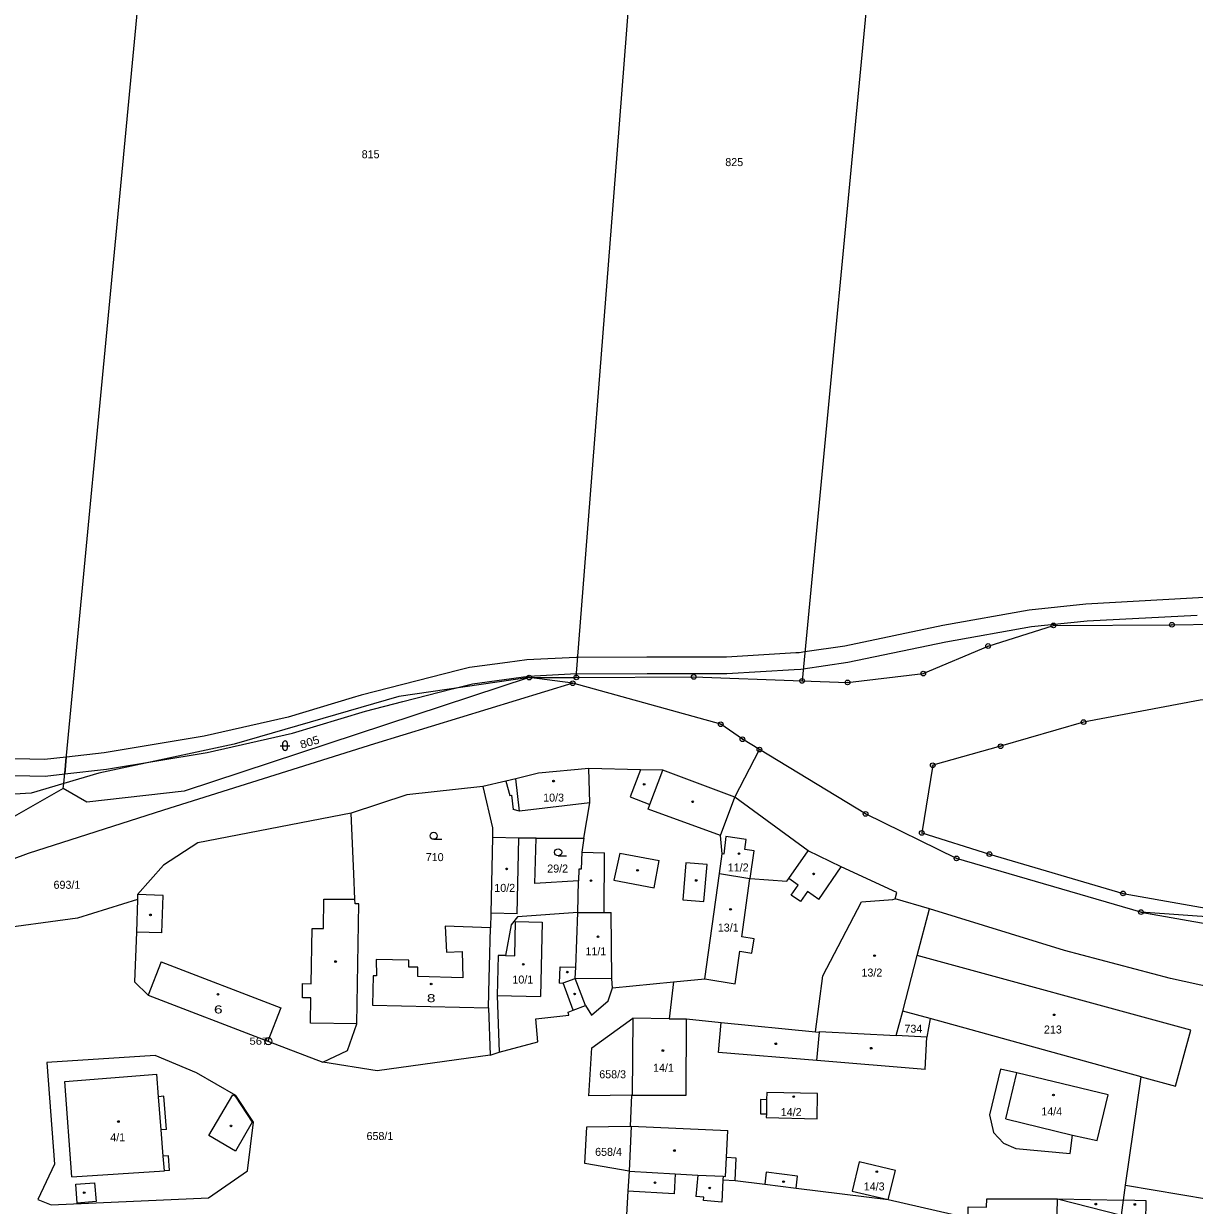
# Model space of a CAD drawing. Extents: x -758887 to -754328, y -1031688 to -1029144.
# Drawn here: x -756406 to -756157.4, y -1030298.3 to -1030047.3 of the extents above; entities that cross this region are included whole.
import ezdxf
from ezdxf.enums import TextEntityAlignment as Align

# ---------------------------------------------------------------- set-up
doc = ezdxf.new("R2010")
doc.units = 0
doc.header["$LTSCALE"] = 0.68
for name, color, linetype, lineweight in [('1', 7, 'Continuous', 25), ('13', 7, 'Continuous', 13), ('3', 7, 'Continuous', 25), ('4', 7, 'Continuous', 13), ('5', 7, 'Continuous', 25), ('8', 7, 'Continuous', 25)]:
    doc.layers.add(name, color=color, linetype=linetype, lineweight=lineweight)
doc.layers.add('2', color=7, linetype='Continuous')

msp = doc.modelspace()

# ---------------------------------------------------------------- linework, layer by layer
at = {"layer": '1'}
for p, q in [((-756298.64, -1030186.19), (-756288.65, -1030186.16)), ((-756289.4, -1030187.39), (-756298.64, -1030186.19)), ((-756254.97, -1030211.62), (-756249.73, -1030201.5)), ((-756397.61, -1030209.77), (-756397.5, -1030208.7)), ((-756308.5, -1030209.34), (-756324.6, -1030211.13)), ((-756324.6, -1030211.13), (-756336.44, -1030214.98)), ((-756239.39, -1030223), (-756254.97, -1030211.62)), ((-756297.13, -1030220.29), (-756287, -1030220.3)), ((-756288.32, -1030236.1), (-756288.15, -1030229.38)), ((-756381.8, -1030232.31), (-756381.84, -1030233.37)), ((-756115.36, -1030239.81), (-756168.69, -1030236.01)), ((-756306.88, -1030239.35), (-756316.51, -1030239.02)), ((-756237.83, -1030261.47), (-756236.27, -1030249.59)), ((-756268, -1030250.87), (-756268.93, -1030258.67)), ((-756307.27, -1030256.38), (-756306.89, -1030266.4)), ((-756220.67, -1030262.26), (-756219.3, -1030257.06)), ((-756213.48, -1030258.66), (-756219.3, -1030257.06)), ((-756268.93, -1030258.67), (-756276.6, -1030258.56)), ((-756342.5, -1030267.88), (-756337.26, -1030265.43)), ((-756306.89, -1030266.4), (-756304.98, -1030265.8)), ((-756276.93, -1030274.93), (-756285.96, -1030275.08)), ((-756186.43, -1030296.97), (-756172.41, -1030297.26)), ((-756186.43, -1030296.97), (-756172.86, -1030300.43)), ((-756172.86, -1030300.43), (-756172.41, -1030297.26))]:
    msp.add_line(p, q, dxfattribs=at)
for points in [[(-756397.5, -1030208.7), (-756385.26, -1030080.23), (-756373.02, -1029951.75)], [(-756288.65, -1030186.16), (-756279.98, -1030074.99), (-756271.3, -1029963.81)], [(-756219.98, -1029969.89), (-756230.34, -1030078.39), (-756240.69, -1030186.89)], [(-755912.98, -1030131.91), (-755941.48, -1030149.18), (-755969.92, -1030165.14), (-755979.24, -1030168.83), (-756000.09, -1030175.58), (-756023.31, -1030180.26), (-756045.55, -1030182.98), (-756110.5, -1030186.46), (-756122.46, -1030187.46), (-756156.09, -1030190.98), (-756180.89, -1030195.65), (-756198.51, -1030200.79), (-756212.93, -1030204.83), (-756215.25, -1030219.21), (-756200.88, -1030223.69), (-756172.51, -1030232.07), (-756144.45, -1030237.03), (-756115.36, -1030239.81)], [(-756397.5, -1030208.7), (-756404.43, -1030210.74), (-756423.36, -1030211.9), (-756445.13, -1030205.02), (-756460.1, -1030199.16), (-756472.56, -1030191.89), (-756481.5, -1030181.55), (-756483.07, -1030159.02)], [(-756397.61, -1030209.77), (-756413.06, -1030218.58), (-756424.18, -1030217.91), (-756448.29, -1030208.09), (-756458.95, -1030202.48), (-756478.73, -1030190.1), (-756487.17, -1030180.84), (-756487.51, -1030172.18)], [(-756240.69, -1030186.89), (-756231.02, -1030187.24), (-756214.93, -1030185.36), (-756201.16, -1030179.49), (-756187.28, -1030175.13), (-756162.13, -1030174.98), (-756134.72, -1030174.56), (-756116.1, -1030171.61), (-756107.99, -1030171.7), (-756103.62, -1030173.4), (-756090.76, -1030175.31), (-756046.25, -1030174.07)], [(-756289.4, -1030187.39), (-756331.47, -1030200.27), (-756376.31, -1030214.36), (-756405.07, -1030223.59), (-756412.88, -1030226.49), (-756423.07, -1030227.94), (-756433.13, -1030224.17), (-756441.53, -1030224.23)], [(-756298.64, -1030186.19), (-756371.89, -1030210.3), (-756392.61, -1030212.65), (-756397.61, -1030209.77)], [(-756298.64, -1030186.19), (-756326.33, -1030190.22), (-756361.32, -1030200.34), (-756390.05, -1030206.51), (-756397.5, -1030208.7)], [(-756249.73, -1030201.5), (-756253.34, -1030199.31), (-756257.96, -1030196.12), (-756289.4, -1030187.39)], [(-756288.65, -1030186.16), (-756263.67, -1030186.07), (-756240.69, -1030186.89)], [(-756168.69, -1030236.01), (-756207.87, -1030224.63), (-756227.19, -1030215.16), (-756249.73, -1030201.5)], [(-756285.94, -1030205.54), (-756296.67, -1030206.53), (-756301.49, -1030207.68), (-756303.63, -1030208.19), (-756308.5, -1030209.34)], [(-756287, -1030220.3), (-756285.78, -1030212.8), (-756285.94, -1030205.54)], [(-756254.97, -1030211.62), (-756270.23, -1030205.88), (-756275.01, -1030205.78), (-756285.94, -1030205.54)], [(-756308.5, -1030209.34), (-756306.42, -1030218.15), (-756306.43, -1030220.16)], [(-756258.25, -1030227.8), (-756257.66, -1030223.64), (-756258.03, -1030219.77), (-756254.97, -1030211.62)], [(-756336.44, -1030214.98), (-756369.05, -1030221.33), (-756376.28, -1030226.02), (-756381.8, -1030232.31)], [(-756337.26, -1030265.43), (-756335.21, -1030259.75), (-756334.8, -1030234.3), (-756335.6, -1030234.29), (-756335.64, -1030233.31), (-756335.87, -1030227.92), (-756336.44, -1030214.98)], [(-756306.43, -1030220.16), (-756306.8, -1030236.25), (-756306.88, -1030239.35)], [(-756297.13, -1030220.29), (-756300.83, -1030220.29), (-756306.43, -1030220.16)], [(-756288.15, -1030229.38), (-756297.43, -1030229.96), (-756297.13, -1030220.29)], [(-756287, -1030220.3), (-756287.49, -1030223.3), (-756287.58, -1030226.9), (-756288.08, -1030226.88), (-756288.15, -1030229.38)], [(-756258.25, -1030227.8), (-756251.77, -1030228.9), (-756251.68, -1030228.91), (-756243.9, -1030229.43), (-756243.5, -1030228.86), (-756239.39, -1030223)], [(-756220.87, -1030233.23), (-756220.54, -1030231.86), (-756232.36, -1030226.44), (-756239.39, -1030223)], [(-756268, -1030250.87), (-756261.35, -1030250.22), (-756258.25, -1030227.8)], [(-756381.84, -1030233.37), (-756394.55, -1030237.3), (-756413.41, -1030239.85)], [(-756381.84, -1030233.37), (-756382.07, -1030240.27), (-756382.44, -1030250.86)], [(-756236.27, -1030249.59), (-756228.08, -1030233.83), (-756221.43, -1030233.35), (-756220.87, -1030233.23)], [(-756219.3, -1030257.06), (-756216.2, -1030245.25), (-756213.6, -1030235.35), (-756220.87, -1030233.23)], [(-756108.96, -1030258.41), (-756110.66, -1030258.34), (-756131.11, -1030256.31), (-756143.73, -1030254.26), (-756162.39, -1030250.16), (-756184.91, -1030244.16), (-756213.6, -1030235.35)], [(-756288.32, -1030236.1), (-756301.15, -1030237.06), (-756302.45, -1030238.75), (-756303.7, -1030245.28), (-756305.25, -1030245.24), (-756305.45, -1030253.74), (-756304.98, -1030265.8)], [(-756286.68, -1030255.9), (-756288.84, -1030250.1), (-756288.75, -1030247.74), (-756288.32, -1030236.1)], [(-756168.69, -1030236.01), (-756107.58, -1030246.78), (-756057.43, -1030250.7), (-755984.58, -1030253.93), (-755948, -1030254.04), (-755899.3, -1030254.19), (-755881.67, -1030257.6), (-755833.91, -1030271.8), (-755782.97, -1030285.7), (-755758.24, -1030294.36)], [(-756316.51, -1030239.02), (-756316.2, -1030244.55), (-756312.9, -1030244.36)], [(-756307.27, -1030256.38), (-756307.13, -1030250.08), (-756307.07, -1030247.55), (-756306.88, -1030239.35)], [(-756312.9, -1030244.36), (-756312.7, -1030249.96), (-756322.31, -1030249.74), (-756322.28, -1030247.74)], [(-756168.68, -1030270.99), (-756161.37, -1030273), (-756158.12, -1030261.08), (-756216.2, -1030245.25)], [(-756331.11, -1030246.12), (-756331.05, -1030249.55), (-756331.81, -1030249.53), (-756331.95, -1030255.83), (-756307.27, -1030256.38)], [(-756322.28, -1030247.74), (-756324.2, -1030247.69), (-756324.17, -1030246.23), (-756331.11, -1030246.12)], [(-756382.44, -1030250.86), (-756379.54, -1030253.67), (-756354.12, -1030263.47), (-756342.5, -1030267.88)], [(-756286.68, -1030255.9), (-756285.43, -1030257.95), (-756281.89, -1030254.87), (-756280.94, -1030252.14), (-756268, -1030250.87)], [(-756304.98, -1030265.8), (-756296.79, -1030263.57), (-756297.23, -1030258.67), (-756290.19, -1030257.94), (-756290.36, -1030257.26), (-756289.27, -1030256.86), (-756286.68, -1030255.9)], [(-756285.96, -1030275.08), (-756285.33, -1030264.89), (-756276.6, -1030258.56)], [(-756276.6, -1030258.56), (-756276.73, -1030274.93), (-756276.93, -1030274.93), (-756277.16, -1030281.48)], [(-756268.93, -1030258.67), (-756265.21, -1030258.72), (-756257.88, -1030259.46), (-756237.83, -1030261.47)], [(-756213.48, -1030258.66), (-756214.17, -1030262.6), (-756220.67, -1030262.26)], [(-756172.41, -1030297.26), (-756171.95, -1030294.02), (-756168.68, -1030270.99), (-756213.48, -1030258.66)], [(-756171.95, -1030294.02), (-756136.72, -1030299.99), (-756110.94, -1030301.63), (-756111.35, -1030284.16), (-756108.96, -1030258.41)], [(-756237.83, -1030261.47), (-756237, -1030261.54), (-756236.99, -1030261.41), (-756220.67, -1030262.26)], [(-756306.89, -1030266.4), (-756330.93, -1030269.74), (-756342.5, -1030267.88)], [(-756277.43, -1030291.05), (-756286.84, -1030289.47), (-756286.36, -1030281.68), (-756277.16, -1030281.48)], [(-756277.16, -1030281.48), (-756276.96, -1030281.48), (-756277.43, -1030291.05)], [(-756220.86, -1030290.89), (-756228.52, -1030289.05), (-756230.01, -1030295.28)], [(-756277.43, -1030291.05), (-756277.68, -1030295.34), (-756278.04, -1030301.63)], [(-756277.43, -1030291.05), (-756267.6, -1030291.62), (-756262.8, -1030291.89), (-756257.46, -1030292.14), (-756257.5, -1030292.9), (-756254.89, -1030293.02), (-756248.59, -1030293.81), (-756241.94, -1030294.65), (-756222.37, -1030297.12), (-756205.42, -1030300.96), (-756205.39, -1030298.66), (-756201.49, -1030298.72), (-756201.46, -1030296.97), (-756186.43, -1030296.97)], [(-756230.01, -1030295.28), (-756222.37, -1030297.12), (-756220.86, -1030290.89)], [(-756187.15, -1030337.79), (-756187.28, -1030336.24), (-756187.11, -1030328.19), (-756186.43, -1030296.97)], [(-756167.68, -1030301.76), (-756167.6, -1030297.36), (-756172.41, -1030297.26)]]:
    msp.add_lwpolyline(points, dxfattribs=at)
for points in [[(-756402.99, -1030297.09), (-756400.2, -1030298.24), (-756366.72, -1030296.7), (-756358.44, -1030291.01), (-756357.22, -1030280.65), (-756360.95, -1030274.96), (-756369.31, -1030270.17), (-756378.05, -1030266.48), (-756401.1, -1030267.97), (-756399.46, -1030289.6)], [(-756178.02, -1030284.55), (-756175.64, -1030274.87), (-756195.04, -1030270.2), (-756198.52, -1030269.37), (-756200.84, -1030279.1), (-756199.99, -1030282.84), (-756197.89, -1030285.09), (-756195.27, -1030286.27), (-756183.75, -1030287.3), (-756183.22, -1030283.41)], [(-756249.53, -1030278.85), (-756248.26, -1030278.87), (-756248.27, -1030279.68), (-756237.45, -1030279.95), (-756237.4, -1030274.6), (-756248.19, -1030274.38), (-756248.21, -1030275.89), (-756249.48, -1030275.87)]]:
    msp.add_lwpolyline(points, close=True, dxfattribs=at)
at = {"layer": '13'}
for points in [[(-756147.68, -1030168.74), (-756180.38, -1030170.62), (-756192.44, -1030171.88), (-756210.77, -1030175.15), (-756231.6, -1030179.5), (-756240.1, -1030180.75), (-756241.27, -1030180.92), (-756241.99, -1030180.96), (-756256.74, -1030181.84), (-756273.62, -1030181.83), (-756288.3, -1030181.92), (-756288.32, -1030181.92), (-756288.63, -1030181.92), (-756299.13, -1030182.44), (-756303.23, -1030182.98), (-756311.34, -1030184.06), (-756313.61, -1030184.64), (-756334.36, -1030189.96), (-756336.21, -1030190.52), (-756349.81, -1030194.63), (-756367.68, -1030198.65), (-756388.89, -1030202.17), (-756396.91, -1030203.09), (-756396.97, -1030203.1), (-756397.3, -1030206.65), (-756397.28, -1030206.65), (-756388.41, -1030205.63), (-756377.73, -1030203.86), (-756367, -1030202.09), (-756348.91, -1030198.01), (-756333.42, -1030193.34), (-756325.5, -1030191.31), (-756315.01, -1030188.61), (-756314.65, -1030188.52), (-756310.68, -1030187.5), (-756298.81, -1030185.92), (-756288.59, -1030185.36), (-756288.53, -1030185.42), (-756273.6, -1030185.33), (-756256.64, -1030185.34), (-756242.36, -1030184.49), (-756240.91, -1030184.4), (-756240.45, -1030184.33), (-756230.98, -1030182.94), (-756210.11, -1030178.59), (-756191.96, -1030175.34), (-756180.1, -1030174.12), (-756156.78, -1030172.92)], [(-756411.37, -1030206.9), (-756401.43, -1030207.12), (-756397.3, -1030206.65), (-756396.97, -1030203.1), (-756401.59, -1030203.62), (-756411.03, -1030203.4)]]:
    msp.add_lwpolyline(points, dxfattribs=at)
at = {"layer": '3'}
for p, q in [((-756351.001, -1030200.171), (-756351.001, -1030201.172)), ((-756349.999, -1030201.172), (-756349.999, -1030200.171)), ((-756351.501, -1030200.671), (-756349.499, -1030200.671)), ((-756318.923, -1030220.56), (-756317.173, -1030220.56)), ((-756292.483, -1030224.07), (-756290.733, -1030224.07))]:
    msp.add_line(p, q, dxfattribs=at)
for centre in [(-756318.9229, -1030219.8098), (-756292.4829, -1030223.3198)]:
    msp.add_circle(centre, 0.75, dxfattribs=at)
for centre, start, end in [((-756350.5, -1030200.1709), 0, 180), ((-756350.5, -1030201.1709), 180, 359.98789)]:
    msp.add_arc(centre, 0.5, start, end, dxfattribs=at)
at = {"layer": '4'}
for p, q in [((-756300.68, -1030214.55), (-756301.49, -1030207.68)), ((-756275.01, -1030205.78), (-756277.19, -1030211.54)), ((-756272.98, -1030213.13), (-756270.23, -1030205.88)), ((-756303.63, -1030208.19), (-756302.74, -1030211.22)), ((-756302.74, -1030211.22), (-756302.39, -1030211.18)), ((-756302.39, -1030211.18), (-756302.02, -1030214.26)), ((-756285.78, -1030212.8), (-756300.68, -1030214.55)), ((-756277.19, -1030211.54), (-756272.98, -1030213.13)), ((-756300.68, -1030214.55), (-756302.02, -1030214.26)), ((-756273.37, -1030214.16), (-756272.98, -1030213.13)), ((-756258.03, -1030219.77), (-756273.37, -1030214.16)), ((-756301.2, -1030236.38), (-756300.83, -1030220.29)), ((-756287.49, -1030223.3), (-756282.67, -1030223.42)), ((-756282.7, -1030236.11), (-756282.67, -1030223.42)), ((-756279.39, -1030223.47), (-756271.02, -1030225.06)), ((-756257.32, -1030223.69), (-756257.66, -1030223.64)), ((-756265.36, -1030225.55), (-756266.03, -1030233.4)), ((-756260.85, -1030225.93), (-756265.36, -1030225.55)), ((-756261.52, -1030233.78), (-756260.85, -1030225.93)), ((-756237.13, -1030233.33), (-756232.36, -1030226.44)), ((-756253.46, -1030241.29), (-756251.77, -1030228.9)), ((-756241.49, -1030230.27), (-756243.5, -1030228.86)), ((-756242.99, -1030232.4), (-756241.49, -1030230.27)), ((-756376.4, -1030232.5), (-756381.8, -1030232.31)), ((-756376.68, -1030240.45), (-756376.4, -1030232.5)), ((-756241.02, -1030233.77), (-756242.99, -1030232.4)), ((-756342.29, -1030239.49), (-756342.23, -1030233.26)), ((-756342.23, -1030233.26), (-756335.64, -1030233.31)), ((-756266.03, -1030233.4), (-756261.52, -1030233.78)), ((-756301.2, -1030236.38), (-756306.8, -1030236.25)), ((-756281.1, -1030250.22), (-756281.2, -1030236.1)), ((-756376.68, -1030240.45), (-756382.07, -1030240.27)), ((-756301.54, -1030238.02), (-756295.89, -1030238.15)), ((-756295.89, -1030238.15), (-756296.25, -1030253.95)), ((-756376.81, -1030246.58), (-756379.54, -1030253.67)), ((-756376.81, -1030246.58), (-756351.39, -1030256.38)), ((-756292.18, -1030251.12), (-756292.06, -1030247.62)), ((-756292.06, -1030247.62), (-756288.75, -1030247.74)), ((-756291.43, -1030251.06), (-756288.84, -1030250.1)), ((-756281.1, -1030250.22), (-756288.84, -1030250.1)), ((-756280.94, -1030252.14), (-756281.1, -1030250.22)), ((-756261.35, -1030250.22), (-756254.92, -1030251.24)), ((-756292.18, -1030251.12), (-756291.43, -1030251.06)), ((-756289.27, -1030256.86), (-756291.43, -1030251.06)), ((-756305.45, -1030253.74), (-756296.25, -1030253.95)), ((-756351.39, -1030256.38), (-756354.12, -1030263.47)), ((-756265.28, -1030274.95), (-756265.21, -1030258.72)), ((-756258.41, -1030265.82), (-756257.88, -1030259.46)), ((-756237.53, -1030267.57), (-756237, -1030261.54)), ((-756214.53, -1030269.49), (-756214.17, -1030262.6)), ((-756237.53, -1030267.57), (-756258.41, -1030265.82)), ((-756214.53, -1030269.49), (-756237.53, -1030267.57)), ((-756397.28, -1030272.01), (-756377.71, -1030270.49)), ((-756377.34, -1030275.24), (-756377.71, -1030270.49)), ((-756197.39, -1030279.92), (-756195.04, -1030270.2)), ((-756395.76, -1030292.28), (-756397.28, -1030272.01)), ((-756376.25, -1030275.15), (-756377.34, -1030275.24)), ((-756376.8, -1030282.3), (-756377.34, -1030275.24)), ((-756375.7, -1030282.21), (-756376.25, -1030275.15)), ((-756276.73, -1030274.93), (-756265.28, -1030274.95)), ((-756248.21, -1030275.89), (-756248.26, -1030278.87)), ((-756197.39, -1030279.92), (-756183.22, -1030283.41)), ((-756375.7, -1030282.21), (-756376.8, -1030282.3)), ((-756376.36, -1030287.9), (-756376.8, -1030282.3)), ((-756276.96, -1030281.48), (-756256.45, -1030282.44)), ((-756375.27, -1030287.82), (-756376.36, -1030287.9)), ((-756376.12, -1030290.99), (-756376.36, -1030287.9)), ((-756375.03, -1030290.91), (-756375.27, -1030287.82)), ((-756256.91, -1030292.17), (-756256.72, -1030288.18)), ((-756254.89, -1030293.02), (-756254.67, -1030288.28)), ((-756395.76, -1030292.28), (-756376.12, -1030290.99)), ((-756375.03, -1030290.91), (-756376.12, -1030290.99)), ((-756262.8, -1030291.89), (-756263.23, -1030296.43)), ((-756257.5, -1030292.9), (-756257.72, -1030297.65)), ((-756257.46, -1030292.14), (-756256.91, -1030292.17)), ((-756248.27, -1030291.28), (-756248.59, -1030293.81)), ((-756241.62, -1030292.12), (-756248.27, -1030291.28)), ((-756241.94, -1030294.65), (-756241.62, -1030292.12)), ((-756261.54, -1030296.59), (-756263.23, -1030296.43)), ((-756261.6, -1030297.29), (-756261.54, -1030296.59)), ((-756257.72, -1030297.65), (-756261.6, -1030297.29))]:
    msp.add_line(p, q, dxfattribs=at)
for points in [[(-756251.68, -1030228.91), (-756250.82, -1030223), (-756252.85, -1030222.73), (-756252.53, -1030220.62), (-756256.84, -1030219.93), (-756257.32, -1030223.69)], [(-756279.39, -1030223.47), (-756280.65, -1030229.23), (-756272.12, -1030230.84), (-756271.02, -1030225.06)], [(-756237.13, -1030233.33), (-756239.53, -1030231.64), (-756241.02, -1030233.77)], [(-756288.32, -1030236.1), (-756282.7, -1030236.11), (-756281.2, -1030236.1)], [(-756346.79, -1030251.2), (-756344.95, -1030251.23), (-756344.74, -1030239.48), (-756342.29, -1030239.49)], [(-756303.7, -1030245.28), (-756301.7, -1030245.32), (-756301.54, -1030238.02)], [(-756254.92, -1030251.24), (-756253.91, -1030244.35), (-756251.34, -1030244.78), (-756250.85, -1030241.71), (-756253.46, -1030241.29)], [(-756344.99, -1030254.26), (-756346.78, -1030254.25), (-756346.79, -1030251.2)], [(-756335.21, -1030259.75), (-756345.11, -1030259.59), (-756344.99, -1030254.26)], [(-756254.67, -1030288.28), (-756256.72, -1030288.18), (-756256.45, -1030282.44)], [(-756267.6, -1030291.62), (-756267.84, -1030295.91), (-756277.68, -1030295.34)]]:
    msp.add_lwpolyline(points, dxfattribs=at)
for points in [[(-756361.6, -1030274.82), (-756361.1, -1030275.12), (-756357.46, -1030280.66), (-756361.05, -1030286.8), (-756366.68, -1030283.52)], [(-756394.94, -1030293.84), (-756390.95, -1030293.53), (-756390.64, -1030297.52), (-756394.63, -1030297.83)]]:
    msp.add_lwpolyline(points, close=True, dxfattribs=at)
at = {"layer": '5'}
for centre in [(-756293.4668, -1030208.1992), (-756274.2168, -1030208.8792), (-756263.9068, -1030212.5892), (-756254.0668, -1030223.5992), (-756303.4368, -1030226.8392), (-756275.6168, -1030227.1592), (-756238.2168, -1030227.9092), (-756285.5068, -1030229.3392), (-756263.1568, -1030229.2992), (-756255.8668, -1030235.4192), (-756379.0868, -1030236.6092), (-756284.0168, -1030241.2692), (-756225.2868, -1030245.2692), (-756339.7668, -1030246.5292), (-756299.8868, -1030247.1192), (-756290.5468, -1030248.7692), (-756319.4568, -1030251.2992), (-756364.7368, -1030253.4792), (-756288.9868, -1030253.4192), (-756187.1168, -1030257.8492), (-756270.2468, -1030265.4392), (-756246.2668, -1030263.9992), (-756225.9868, -1030264.9392), (-756242.4468, -1030275.2292), (-756187.2768, -1030274.8892), (-756385.8768, -1030280.5292), (-756361.9768, -1030281.4392), (-756267.7868, -1030286.6792), (-756244.6168, -1030293.2792), (-756224.7968, -1030291.1892), (-756393.1568, -1030295.6292), (-756271.9068, -1030293.5192), (-756260.2968, -1030294.6392), (-756178.2868, -1030298.0692), (-756169.9968, -1030298.1392)]:
    msp.add_circle(centre, 0.175, dxfattribs=at)
at = {"layer": '8'}
for centre, radius in [((-756187.28, -1030175.1299), 0.5), ((-756187.28, -1030175.1299), 0.0303), ((-756162.13, -1030174.9799), 0.5), ((-756162.13, -1030174.9799), 0.0303), ((-756201.16, -1030179.4899), 0.5), ((-756201.16, -1030179.4899), 0.0303), ((-756214.93, -1030185.3599), 0.5), ((-756298.64, -1030186.1899), 0.5), ((-756298.64, -1030186.1899), 0.0303), ((-756289.4, -1030187.3899), 0.5), ((-756289.4, -1030187.3899), 0.0303), ((-756288.65, -1030186.1599), 0.5), ((-756288.65, -1030186.1599), 0.0303), ((-756263.67, -1030186.0699), 0.5), ((-756263.67, -1030186.0699), 0.0303), ((-756240.69, -1030186.8899), 0.5), ((-756240.69, -1030186.8899), 0.0303), ((-756231.02, -1030187.2399), 0.5), ((-756231.02, -1030187.2399), 0.0303), ((-756214.93, -1030185.3599), 0.0303), ((-756180.89, -1030195.6499), 0.5), ((-756257.96, -1030196.1199), 0.5), ((-756257.96, -1030196.1199), 0.0303), ((-756180.89, -1030195.6499), 0.0303), ((-756253.34, -1030199.3099), 0.5), ((-756253.34, -1030199.3099), 0.0303), ((-756198.51, -1030200.7899), 0.5), ((-756249.73, -1030201.4999), 0.5), ((-756249.73, -1030201.4999), 0.0303), ((-756198.51, -1030200.7899), 0.0303), ((-756212.93, -1030204.8299), 0.5), ((-756212.93, -1030204.8299), 0.0303), ((-756227.19, -1030215.1599), 0.5), ((-756227.19, -1030215.1599), 0.0303), ((-756215.25, -1030219.2099), 0.5), ((-756215.25, -1030219.2099), 0.0303), ((-756207.87, -1030224.6299), 0.5), ((-756207.87, -1030224.6299), 0.0303), ((-756200.88, -1030223.6899), 0.5), ((-756200.88, -1030223.6899), 0.0303), ((-756172.51, -1030232.0699), 0.5), ((-756172.51, -1030232.0699), 0.0303), ((-756168.69, -1030236.0099), 0.5), ((-756168.69, -1030236.0099), 0.0303), ((-756354.04, -1030263.4398), 0.75), ((-756354.04, -1030263.4398), 0.03)]:
    msp.add_circle(centre, radius, dxfattribs=at)

# ---------------------------------------------------------------- texts
at = {"layer": '2'}
for s, p in [('815', (-756332.319, -1030075.856)), ('825', (-756255.089, -1030077.526)), ('10/3', (-756293.46, -1030212.55)), ('710', (-756318.709, -1030225.19)), ('29/2', (-756292.59, -1030227.62)), ('11/2', (-756254.24, -1030227.39)), ('693/1', (-756396.82, -1030231.07)), ('10/2', (-756303.83, -1030231.73)), ('13/1', (-756256.36, -1030240.16)), ('11/1', (-756284.47, -1030245.2)), ('13/2', (-756225.85, -1030249.72)), ('10/1', (-756299.99, -1030251.21)), ('734', (-756217.039, -1030261.65)), ('213', (-756187.409, -1030261.82)), ('658/3', (-756280.91, -1030271.33)), ('14/1', (-756270.12, -1030269.95)), ('14/2', (-756242.99, -1030279.36)), ('14/4', (-756187.65, -1030279.23)), ('4/1', (-756386.039, -1030284.73)), ('658/1', (-756330.34, -1030284.45)), ('658/4', (-756281.79, -1030287.81)), ('14/3', (-756225.36, -1030295.16))]:
    msp.add_text(s, height=1.7, dxfattribs=at).set_placement(p, align=Align.CENTER)
at = {"layer": '2', "width": 1.1}
msp.add_text('805', height=1.7, rotation=17, dxfattribs=at).set_placement((-756345.0195, -1030200.7139), align=Align.CENTER)
at = {"layer": '2', "width": 1.45}
for s, p in [('8', (-756319.45, -1030255.16)), ('6', (-756364.67, -1030257.56))]:
    msp.add_text(s, height=1.7, dxfattribs=at).set_placement(p, align=Align.CENTER)
at = {"layer": '8', "width": 1.2}
msp.add_text('567', height=1.5, dxfattribs=at).set_placement((-756354.04, -1030264.19), align=Align.RIGHT)

doc.saveas('drawing.dxf')
